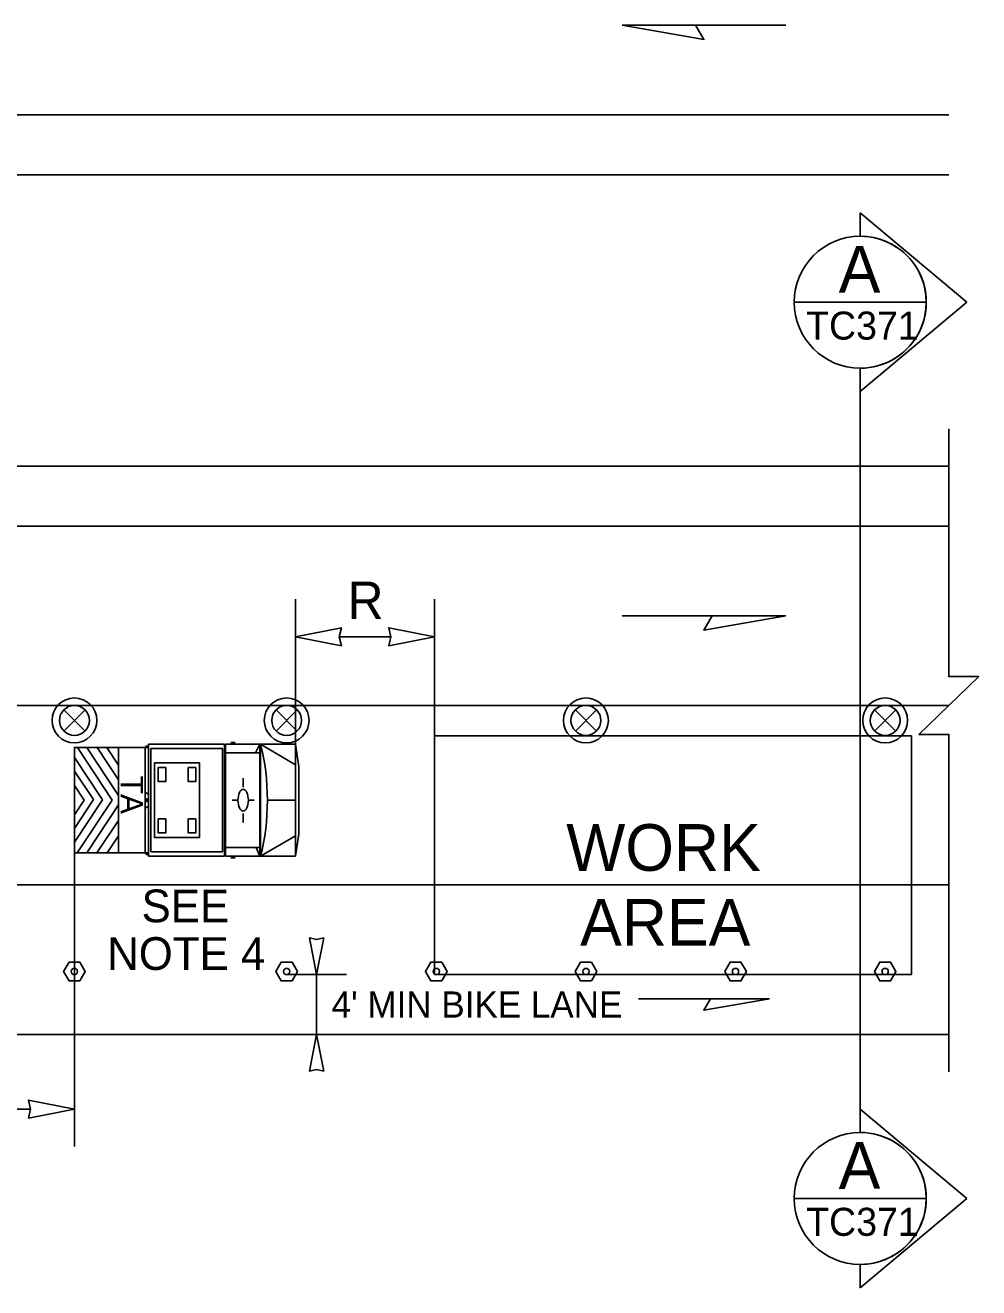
# Model space of a CAD drawing. Extents: x 99958 to 100136, y 99935 to 100013.
# Drawn here: x 100045.58 to 100047.619, y 99973.53 to 99976.232 of the extents above; entities that cross this region are included whole.
import ezdxf

# ---------------------------------------------------------------- set-up
doc = ezdxf.new("R2010")
doc.units = 0
for name, color, linetype in [('RD_ED_ShoulderPavedEdge', 7, 'Continuous'), ('RD_MK_LineEdgeYellow', 7, 'Continuous'), ('RD_MK_LineLane', 7, 'Continuous'), ('SH_TI_WZSectionCut', 7, 'Continuous'), ('TR_WZ_TrafficSafetyDrum', 7, 'Continuous'), ('TR_WZ_TransportableAttenuator', 7, 'Continuous'), ('TR_WZ_TubularMarker', 7, 'Continuous'), ('TR_WZ_WorkAreaLabel', 7, 'Continuous'), ('TR_WZ_WorkZoneDetails', 7, 'Continuous'), ('TR_WZ_WorkZoneTextCurrent', 7, 'Continuous')]:
    doc.layers.add(name, color=color, linetype=linetype)

msp = doc.modelspace()

# ---------------------------------------------------------------- linework, layer by layer
at = {"layer": 'RD_ED_ShoulderPavedEdge'}
for p, q in [((100047.555, 99975.9124), (100044.8819, 99975.9124)), ((100047.555, 99975.2885), (100044.8819, 99975.2885)), ((100044.6319, 99974.0724), (100047.555, 99974.0724))]:
    msp.add_line(p, q, dxfattribs=at)
at = {"layer": 'RD_MK_LineEdgeYellow'}
for p, q in [((100044.8819, 99976.0404), (100047.555, 99976.0404)), ((100044.8819, 99975.1604), (100047.555, 99975.1604)), ((100044.8819, 99974.3925), (100047.555, 99974.3925))]:
    msp.add_line(p, q, dxfattribs=at)
at = {"layer": 'RD_MK_LineLane'}
msp.add_lwpolyline([(100047.555, 99974.7765), (100040.32, 99974.7765)], dxfattribs=at)
at = {"layer": 'SH_TI_WZSectionCut'}
for p, q in [((100047.3657, 99975.7808), (100047.3657, 99975.8307)), ((100047.3657, 99975.8307), (100047.5938, 99975.6396)), ((100047.5938, 99975.6396), (100047.3657, 99975.4484)), ((100047.3657, 99975.4484), (100047.3657, 99975.4984)), ((100047.3657, 99975.4485), (100047.3657, 99973.9125)), ((100047.3657, 99973.9125), (100047.3657, 99973.8625)), ((100047.5939, 99973.7213), (100047.3657, 99973.9125)), ((100047.3657, 99973.5302), (100047.5939, 99973.7213)), ((100047.3657, 99973.5801), (100047.3657, 99973.5302))]:
    msp.add_line(p, q, dxfattribs=at)
for points in [[(100047.2245, 99975.6396), (100047.5069, 99975.6396)], [(100047.2245, 99973.7213), (100047.5069, 99973.7213)]]:
    msp.add_lwpolyline(points, dxfattribs=at)
for centre in [(100047.3657, 99975.6396), (100047.3657, 99973.7213)]:
    msp.add_circle(centre, 0.1412, dxfattribs=at)
for centre in [(100047.3657, 99975.6396), (100047.3657, 99973.7213)]:
    msp.add_arc(centre, 0.1412, 269.9978, 90.0022, dxfattribs=at)
at = {"layer": 'TR_WZ_TrafficSafetyDrum'}
for p, q in [((100045.7076, 99974.7671), (100045.6623, 99974.7218)), ((100045.6623, 99974.7671), (100045.7076, 99974.7218)), ((100046.1163, 99974.7671), (100046.1615, 99974.7218)), ((100046.1615, 99974.7671), (100046.1163, 99974.7218)), ((100046.7563, 99974.7671), (100046.8015, 99974.7218)), ((100046.8015, 99974.7671), (100046.7563, 99974.7218)), ((100047.3963, 99974.7671), (100047.4415, 99974.7218)), ((100047.4415, 99974.7671), (100047.3963, 99974.7218))]:
    msp.add_line(p, q, dxfattribs=at)
for centre, radius in [((100045.685, 99974.7445), 0.048), ((100045.685, 99974.7445), 0.048), ((100046.1389, 99974.7445), 0.048), ((100046.1389, 99974.7445), 0.048), ((100046.7789, 99974.7445), 0.048), ((100046.7789, 99974.7445), 0.048), ((100047.4189, 99974.7445), 0.048), ((100047.4189, 99974.7445), 0.048), ((100045.685, 99974.7445), 0.032), ((100046.1389, 99974.7445), 0.032), ((100046.7789, 99974.7445), 0.032), ((100047.4189, 99974.7445), 0.032)]:
    msp.add_circle(centre, radius, dxfattribs=at)
at = {"layer": 'TR_WZ_TransportableAttenuator'}
for p, q in [((100045.766, 99974.5739), (100045.6912, 99974.6866)), ((100045.6912, 99974.6866), (100045.7116, 99974.6866)), ((100045.6912, 99974.6866), (100045.766, 99974.5739)), ((100045.7116, 99974.6866), (100045.6912, 99974.6866)), ((100045.7116, 99974.6866), (100045.7793, 99974.5838)), ((100045.7793, 99974.5838), (100045.7116, 99974.6866)), ((100045.7793, 99974.6171), (100045.7337, 99974.6866)), ((100045.7337, 99974.6866), (100045.7541, 99974.6866)), ((100045.7541, 99974.6866), (100045.7337, 99974.6866)), ((100045.7337, 99974.6866), (100045.7793, 99974.6171)), ((100045.7541, 99974.6866), (100045.7793, 99974.6484)), ((100045.7793, 99974.6484), (100045.7541, 99974.6866)), ((100045.7793, 99974.4613), (100045.7793, 99974.6866)), ((100045.8437, 99974.6866), (100045.7793, 99974.6866)), ((100045.8361, 99974.6824), (100045.8361, 99974.4649)), ((100045.8396, 99974.6897), (100045.8432, 99974.6897)), ((100045.8432, 99974.6897), (100045.8432, 99974.4576)), ((100045.8437, 99974.6937), (100046.0062, 99974.6937)), ((100045.8437, 99974.6937), (100045.8437, 99974.4537)), ((100045.8437, 99974.6862), (100045.8437, 99974.4613)), ((100045.8483, 99974.6841), (100045.8483, 99974.4633)), ((100045.8483, 99974.6841), (100046.0016, 99974.6841)), ((100046.0016, 99974.6841), (100046.0016, 99974.4633)), ((100046.0062, 99974.6937), (100046.0062, 99974.4537)), ((100046.0084, 99974.6937), (100046.0084, 99974.4537)), ((100046.1576, 99974.6937), (100046.0084, 99974.6937)), ((100046.0817, 99974.6751), (100046.0084, 99974.6751)), ((100046.0288, 99974.6971), (100046.0198, 99974.6971)), ((100046.0817, 99974.6937), (100046.0722, 99974.6751)), ((100046.0817, 99974.6937), (100046.0817, 99974.4537)), ((100046.083, 99974.6937), (100046.083, 99974.4537)), ((100046.1576, 99974.6497), (100046.083, 99974.6937)), ((100046.1576, 99974.6937), (100046.1576, 99974.4537)), ((100046.1576, 99974.6937), (100046.165, 99974.6452)), ((100045.685, 99974.6651), (100045.7451, 99974.5746)), ((100045.685, 99974.636), (100045.685, 99974.6651)), ((100045.7451, 99974.5746), (100045.685, 99974.6651)), ((100045.685, 99974.6651), (100045.685, 99974.636)), ((100045.7793, 99974.6484), (100045.7793, 99974.6171)), ((100045.7793, 99974.6171), (100045.7793, 99974.6484)), ((100045.7258, 99974.5749), (100045.685, 99974.636)), ((100045.685, 99974.636), (100045.7258, 99974.5749)), ((100046.0459, 99974.6212), (100046.0459, 99974.6018)), ((100046.165, 99974.6452), (100046.165, 99974.5021)), ((100045.685, 99974.605), (100045.7058, 99974.574)), ((100045.685, 99974.5426), (100045.685, 99974.605)), ((100045.7058, 99974.574), (100045.685, 99974.605)), ((100045.685, 99974.605), (100045.685, 99974.5426)), ((100045.685, 99974.5135), (100045.7258, 99974.5749)), ((100045.7258, 99974.5749), (100045.685, 99974.5135)), ((100045.7451, 99974.5746), (100045.685, 99974.484)), ((100045.685, 99974.484), (100045.7451, 99974.5746)), ((100045.7058, 99974.574), (100045.685, 99974.5426)), ((100045.685, 99974.5426), (100045.7058, 99974.574)), ((100045.6911, 99974.4611), (100045.766, 99974.5739)), ((100045.766, 99974.5739), (100045.6911, 99974.4611)), ((100045.7793, 99974.5838), (100045.7793, 99974.5638)), ((100045.7793, 99974.5638), (100045.7793, 99974.5838)), ((100045.8361, 99974.5906), (100045.8432, 99974.5861)), ((100045.838, 99974.5737), (100045.8413, 99974.5737)), ((100045.8396, 99974.577), (100045.8396, 99974.5703)), ((100046.022, 99974.5738), (100046.032, 99974.5738)), ((100046.0347, 99974.5732), (100046.0347, 99974.5732)), ((100046.0697, 99974.5738), (100046.0597, 99974.5738)), ((100046.1576, 99974.5737), (100046.0977, 99974.5737)), ((100045.7793, 99974.5638), (100045.7112, 99974.4611)), ((100045.7112, 99974.4611), (100045.7793, 99974.5638)), ((100045.8361, 99974.5568), (100045.8432, 99974.5613)), ((100046.0459, 99974.5261), (100046.0459, 99974.5455)), ((100045.685, 99974.484), (100045.685, 99974.5135)), ((100045.685, 99974.5135), (100045.685, 99974.484)), ((100045.7332, 99974.4611), (100045.7793, 99974.5306)), ((100045.7793, 99974.5306), (100045.7332, 99974.4611)), ((100045.7793, 99974.5306), (100045.7793, 99974.4974)), ((100045.7793, 99974.4974), (100045.7793, 99974.5306)), ((100045.7793, 99974.4974), (100045.7548, 99974.4611)), ((100045.7548, 99974.4611), (100045.7793, 99974.4974)), ((100046.1576, 99974.4976), (100046.083, 99974.4537)), ((100046.1576, 99974.4537), (100046.165, 99974.5021)), ((100045.7112, 99974.4611), (100045.6911, 99974.4611)), ((100045.6911, 99974.4611), (100045.7112, 99974.4611)), ((100045.7548, 99974.4611), (100045.7332, 99974.4611)), ((100045.7332, 99974.4611), (100045.7548, 99974.4611)), ((100045.8437, 99974.4613), (100045.7793, 99974.4613)), ((100045.8396, 99974.4576), (100045.8432, 99974.4576)), ((100045.8483, 99974.4633), (100046.0016, 99974.4633)), ((100046.0817, 99974.4723), (100046.0084, 99974.4723)), ((100046.0738, 99974.4723), (100046.0817, 99974.4537)), ((100045.8437, 99974.4537), (100046.0062, 99974.4537)), ((100046.1576, 99974.4537), (100046.0084, 99974.4537)), ((100046.0288, 99974.4503), (100046.0198, 99974.4503))]:
    msp.add_line(p, q, dxfattribs=at)
for points in [[(100045.7793, 99974.4611), (100045.685, 99974.4611), (100045.685, 99974.6866), (100045.7793, 99974.6866)], [(100045.8563, 99974.6537), (100045.9523, 99974.6537), (100045.9523, 99974.4937), (100045.8563, 99974.4937)], [(100045.8643, 99974.6437), (100045.8803, 99974.6437), (100045.8803, 99974.6137), (100045.8643, 99974.6137)], [(100045.9443, 99974.6437), (100045.9283, 99974.6437), (100045.9283, 99974.6137), (100045.9443, 99974.6137)], [(100045.8643, 99974.5337), (100045.8803, 99974.5337), (100045.8803, 99974.5037), (100045.8643, 99974.5037)], [(100045.9443, 99974.5337), (100045.9283, 99974.5337), (100045.9283, 99974.5037), (100045.9443, 99974.5037)]]:
    msp.add_lwpolyline(points, close=True, dxfattribs=at)
msp.add_lwpolyline([(100045.7793, 99974.6866), (100045.685, 99974.6866), (100045.685, 99974.4611), (100045.7793, 99974.4613)], dxfattribs=at)
for centre, major_axis, start_param, end_param in [((100045.8396, 99974.6824), (0, 0.00732), 6.283185, 7.853982), ((100045.9764, 99974.5736), (0, 0.2519), 4.215852, 5.209111), ((100045.8396, 99974.4649), (0, -0.00732), 4.712389, 6.283185)]:
    msp.add_ellipse(centre, major_axis=major_axis, ratio=0.481608, start_param=start_param, end_param=end_param, dxfattribs=at)
for centre, major_axis in [((100046.0459, 99974.5737), (0, -0.0231)), ((100045.8396, 99974.5737), (0, -0.00338))]:
    msp.add_ellipse(centre, major_axis=major_axis, ratio=0.481608, dxfattribs=at)
at = {"layer": 'TR_WZ_TubularMarker'}
for points in [[(100045.6619, 99974.2071), (100045.6734, 99974.2271), (100045.6965, 99974.2271), (100045.7081, 99974.2071), (100045.6965, 99974.1871), (100045.6734, 99974.1871)], [(100046.1158, 99974.2071), (100046.1274, 99974.2271), (100046.1505, 99974.2271), (100046.162, 99974.2071), (100046.1505, 99974.1871), (100046.1274, 99974.1871)], [(100046.4358, 99974.2071), (100046.4474, 99974.2271), (100046.4705, 99974.2271), (100046.482, 99974.2071), (100046.4705, 99974.1871), (100046.4474, 99974.1871)], [(100046.7558, 99974.2071), (100046.7674, 99974.2271), (100046.7905, 99974.2271), (100046.802, 99974.2071), (100046.7905, 99974.1871), (100046.7674, 99974.1871)], [(100047.0758, 99974.2071), (100047.0874, 99974.2271), (100047.1105, 99974.2271), (100047.122, 99974.2071), (100047.1105, 99974.1871), (100047.0874, 99974.1871)], [(100047.3958, 99974.2071), (100047.4074, 99974.2271), (100047.4305, 99974.2271), (100047.442, 99974.2071), (100047.4305, 99974.1871), (100047.4074, 99974.1871)]]:
    msp.add_lwpolyline(points, close=True, dxfattribs=at)
for points in [[(100045.6734, 99974.1871), (100045.6965, 99974.1871), (100045.7081, 99974.2071), (100045.6965, 99974.2271), (100045.6734, 99974.2271), (100045.6619, 99974.2071), (100045.6734, 99974.1871)], [(100046.1274, 99974.1871), (100046.1505, 99974.1871), (100046.162, 99974.2071), (100046.1505, 99974.2271), (100046.1274, 99974.2271), (100046.1158, 99974.2071), (100046.1274, 99974.1871)], [(100046.4474, 99974.1871), (100046.4705, 99974.1871), (100046.482, 99974.2071), (100046.4705, 99974.2271), (100046.4474, 99974.2271), (100046.4358, 99974.2071), (100046.4474, 99974.1871)], [(100046.7674, 99974.1871), (100046.7905, 99974.1871), (100046.802, 99974.2071), (100046.7905, 99974.2271), (100046.7674, 99974.2271), (100046.7558, 99974.2071), (100046.7674, 99974.1871)], [(100047.0874, 99974.1871), (100047.1105, 99974.1871), (100047.122, 99974.2071), (100047.1105, 99974.2271), (100047.0874, 99974.2271), (100047.0758, 99974.2071), (100047.0874, 99974.1871)], [(100047.4074, 99974.1871), (100047.4305, 99974.1871), (100047.442, 99974.2071), (100047.4305, 99974.2271), (100047.4074, 99974.2271), (100047.3958, 99974.2071), (100047.4074, 99974.1871)]]:
    msp.add_lwpolyline(points, dxfattribs=at)
for centre in [(100045.685, 99974.2071), (100046.1389, 99974.2071), (100046.4589, 99974.2071), (100046.7789, 99974.2071), (100047.0989, 99974.2071), (100047.4189, 99974.2071)]:
    msp.add_circle(centre, 0.00667, dxfattribs=at)
at = {"layer": 'TR_WZ_WorkZoneDetails'}
for p, q in [((100047.0136, 99976.2324), (100047.2065, 99976.2324)), ((100046.1576, 99974.6937), (100046.1576, 99975.0037)), ((100046.4554, 99974.7125), (100046.4554, 99975.0037)), ((100047.0492, 99974.9684), (100046.8563, 99974.9684)), ((100046.3616, 99974.9236), (100046.2514, 99974.9236)), ((100045.685, 99974.4611), (100045.685, 99973.8325)), ((100046.2669, 99974.2004), (100046.1389, 99974.2004)), ((100046.2029, 99974.0724), (100046.2029, 99974.2004)), ((100047.0457, 99974.1488), (100046.8914, 99974.1488)), ((100046.2669, 99974.0724), (100046.1389, 99974.0724)), ((100044.9787, 99973.9125), (100045.5912, 99973.9125))]:
    msp.add_line(p, q, dxfattribs=at)
for points in [[(100046.8563, 99976.2324), (100047.0314, 99976.2016), (100047.0136, 99976.2324)], [(100047.2065, 99974.9684), (100047.0314, 99974.9376), (100047.0492, 99974.9684)], [(100046.1576, 99974.9236), (100046.2559, 99974.9429), (100046.2514, 99974.9236), (100046.2559, 99974.9044)], [(100046.4554, 99974.9236), (100046.3571, 99974.9429), (100046.3616, 99974.9236), (100046.3571, 99974.9044)], [(100046.4554, 99974.2004), (100046.4554, 99974.7114), (100047.475, 99974.7114), (100047.475, 99974.2004)], [(100046.2029, 99974.2004), (100046.2183, 99974.2791), (100046.2029, 99974.2754), (100046.1875, 99974.2791)], [(100047.1714, 99974.1488), (100047.0314, 99974.1241), (100047.0457, 99974.1488)], [(100046.2029, 99974.0724), (100046.2183, 99973.9938), (100046.2029, 99973.9975), (100046.1875, 99973.9938)], [(100045.685, 99973.9125), (100045.5867, 99973.9317), (100045.5912, 99973.9125), (100045.5867, 99973.8932)]]:
    msp.add_lwpolyline(points, close=True, dxfattribs=at)
msp.add_lwpolyline([(100047.555, 99973.9924), (100047.555, 99974.7145), (100047.491, 99974.7145), (100047.619, 99974.8384), (100047.555, 99974.8384), (100047.555, 99975.3685)], dxfattribs=at)

# ---------------------------------------------------------------- texts
at = {"layer": 'SH_TI_WZSectionCut'}
for s, height, rotation, p in [('A', 0.1, 0.01, (100047.3195, 99975.6602)), ('TC371', 0.06, 360, (100047.2498, 99975.5596)), ('A', 0.1, 0.01, (100047.3195, 99973.7419)), ('TC371', 0.06, 360, (100047.2499, 99973.6413))]:
    msp.add_text(s, height=height, rotation=rotation, dxfattribs=at).set_placement(p)
at = {"layer": 'TR_WZ_TransportableAttenuator'}
msp.add_text('TA', height=0.048, rotation=270, dxfattribs=at).set_placement((100045.7837, 99974.6263))
at = {"layer": 'TR_WZ_WorkAreaLabel'}
for s, p in [('WORK', (100046.7369, 99974.4225)), ('AREA', (100046.7665, 99974.2624))]:
    msp.add_text(s, height=0.1, dxfattribs=at).set_placement(p)
at = {"layer": 'TR_WZ_WorkZoneTextCurrent'}
for s, height, p in [('R', 0.08, (100046.2689, 99974.9617)), ('SEE', 0.07, (100045.8286, 99974.3125)), ('NOTE 4', 0.07, (100045.755, 99974.2105)), ("4' MIN BIKE LANE", 0.056, (100046.2349, 99974.1084))]:
    msp.add_text(s, height=height, dxfattribs=at).set_placement(p)

doc.saveas('drawing.dxf')
